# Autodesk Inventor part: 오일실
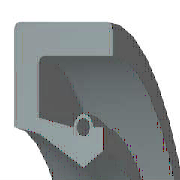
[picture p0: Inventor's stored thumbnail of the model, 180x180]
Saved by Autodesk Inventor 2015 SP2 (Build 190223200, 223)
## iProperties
IsCustomPart: 0
Created: 2009-02
Part Number: 오일실
Material: 고무
Description: 오일-실
Document SubType Name: Modeling
Standard: KS B 2804
Designer: 한국산업디자인학원 [http://gmhk.co.kr]
Standards Organization: KS
Language: ko-KR
Size Designation: S - 17 30 8
Categories: <MemberInstance><Categories><Category DisplayName="샤프트 부품" InternalName="7f7aeb1f-a693-4053-b835-cee3144e0d98" Mnemonic="SHFT"><Category DisplayName="실링" Intern
Density: 0.93 g/cm^3
Appearance: 고무 - 검은색 - 버전 1.1
Author: pww
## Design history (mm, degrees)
revolve "본체" stored, may be unused: angle "d17" = 90 deg
revolve "스프링1" stored, may be unused: angle "d18" = 90 deg
sketch "스케치2"
  geometry: L1 (18.559, 0)-(-18.661, 0); L2 (-18.661, 0)-(-18.661, -22.709); L3 (-18.661, -22.709)-(18.559, -22.709); L4 (18.559, -22.709)-(18.559, 0); 1 further point
  constraints: 8 end point, 2 parallel, 1 horizontal, 1 perpendicular
extrude "돌출1" cut sketch "스케치2" distance "d35" = 123; taper "d36" = 0 deg
body "Solid1"
sketch "스케치1"
  geometry: L1 (0, 15)-(8, 15); L2 (8, 15)-(8, 13.75); L3 (8, 13.75)-(1.75, 13.75); L4 (0, 15)-(0, 10.6); L5 (0, 10.6)-(1.75, 10.25); L6 (1.75, 10.25)-(4.9, 8.5); L7 (4.9, 8.5)-(0, 8.5); L8 (6.3, 9.375)-(6.3, 10.6); L9 (0, 0)-(9.586, 0) reference; L10 (4.9, 8.5)-(6.3, 9.375); L11 (0, 18)-(0, -3) reference; L12 (-1.917, 0)-(11.503, 0) reference; L13 (4.2, 10.6)-(1.75, 11.09); L14 (1.75, 11.09)-(1.75, 13.75); L15 (6.3, 10.6)-(5.6, 10.6); C1 r 0.455 at (4.9, 10.6); A1 r 0.7 centre (4.9, 10.6) between (5.6, 10.6) and (4.2, 10.6)
  constraints: 26 end point, 5 horizontal alignment, 4 perpendicular, 2 centre point, 2 collinear, 2 horizontal, 2 parallel, 2 point on circle, 2 point on line, 2 vertical alignment, 1 coincident
  dimensions: "d0" = 30 diameter of L1 L9 (= SD2); "d1" = 18.75 diameter of L8.start L9 (= ABDM); "d2" = 1.25 distance of L1.end L2.end (computed from SD); "d3" = 0.91 diameter of C1 (= SPDI); "d4" = 1.4 diameter of A1 (= SPDA); "d5" = 17 diameter of L6.end L9 (= NND); "d6" = 20.5 diameter of L5.end L9 (= TKDM); "d7" = 21.2 diameter of L4.end L9 (= HLDM); "d8" = 4.9 distance from line of C1.centre L4 (= SPDST); "d9" = 6.3 distance between parallel lines of L8 L4 (= SDI); "d10" = 8 distance between parallel lines of L2 L4 (= SWDT); "d12" = 1.75 distance between parallel lines of L14 L4 (= SD)
fillet "모깎기1" dims "d11" = 0.3 (= RR)
other parameters: "SD2" = 30 [user parameter; used in 1 equation term], "SWDT" = 8 [user parameter; used in 1 equation term], "RR" = 0.3 [user parameter; used in 1 equation term], "SD" = 1.75 [user parameter; used in 2 equation terms], "NND" = 17 [user parameter; used in 1 equation term], "SPDA" = 1.4 [user parameter; used in 1 equation term], "SPDI" = 0.91 [user parameter; used in 1 equation term], "TKDM" = 20.5 [user parameter; used in 1 equation term], "HLDM" = 21.2 [user parameter; used in 1 equation term], "ABDM" = 18.75 [user parameter; used in 1 equation term], "SDI" = 6.3 [user parameter; used in 1 equation term], "SPDST" = 4.9 [user parameter; used in 1 equation term], "d13" = 0, "d14" = 0, "d15" = 0, "LAB" = 0.35 [user parameter]
